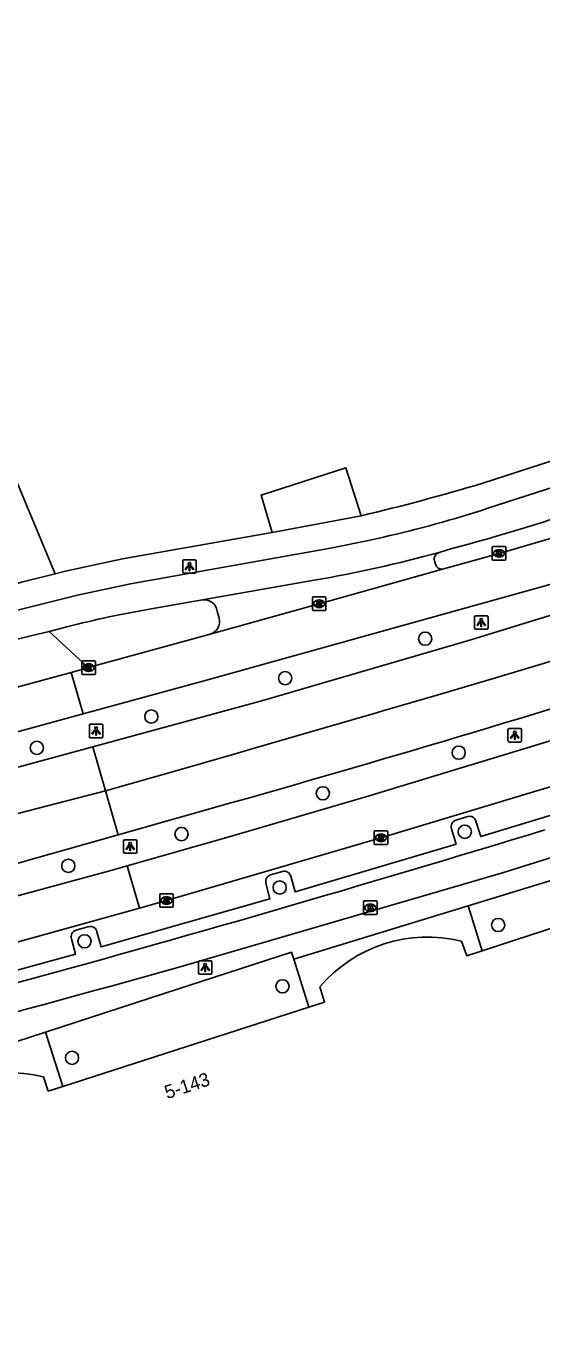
# Model space of a CAD drawing. Extents: x 159265 to 160143, y 383413 to 384319.
# Drawn here: x 159453.2 to 159491.4, y 383990 to 384086.5 of the extents above; entities that cross this region are included whole.
import ezdxf

# ---------------------------------------------------------------- set-up
doc = ezdxf.new("R2010")
doc.units = 0
for name, color, linetype in [('IMGEO_Boom', 7, 'Continuous'), ('IMGEO_Brandkraan', 7, 'Continuous'), ('IMGEO_Fietspad_gesloten', 7, 'Continuous'), ('IMGEO_Groenvoorziening', 7, 'Continuous'), ('IMGEO_Hek', 7, 'Continuous'), ('IMGEO_Kolk', 7, 'Continuous'), ('IMGEO_Lichtpunt', 7, 'Continuous'), ('IMGEO_OVBaan_gesloten', 7, 'Continuous'), ('IMGEO_Pand', 7, 'Continuous'), ('IMGEO_Pand_nummerreeks', 7, 'Continuous'), ('IMGEO_Parkeervlak_open', 7, 'Continuous'), ('IMGEO_Rijbaan_lokaal_gesloten', 7, 'Continuous'), ('IMGEO_Rijbaan_lokaal_open', 7, 'Continuous'), ('IMGEO_Voetpad_open', 7, 'Continuous')]:
    doc.layers.add(name, color=color, linetype=linetype)

msp = doc.modelspace()

# ---------------------------------------------------------------- linework, layer by layer
at = {"layer": 'IMGEO_Boom'}
for centre in [(159482.731, 384041.176), (159472.376, 384038.258), (159462.483, 384035.417), (159454.018, 384033.101), (159485.212, 384032.747), (159475.168, 384029.742), (159464.709, 384026.726), (159485.657, 384026.899), (159456.346, 384024.381), (159471.973, 384022.776), (159488.134, 384020.001), (159457.543, 384018.793), (159472.186, 384015.466), (159456.619, 384010.17)]:
    msp.add_circle(centre, 0.489, dxfattribs=at)
at = {"layer": 'IMGEO_Brandkraan'}
for p, q in [((159478.17, 384020.849), (159478.17, 384021.701)), ((159478.245, 384021.775), (159479.097, 384021.775)), ((159478.658, 384021.555), (159478.683, 384021.555)), ((159479.171, 384021.701), (159479.171, 384020.849)), ((159479.097, 384020.775), (159478.245, 384020.775)), ((159478.681, 384020.995), (159478.656, 384020.995))]:
    msp.add_line(p, q, dxfattribs=at)
for points in [[(159478.17, 384020.849), (159478.17, 384021.701)], [(159478.245, 384021.775), (159479.097, 384021.775)], [(159478.518, 384021.475), (159478.518, 384021.075), (159478.731, 384021.075)], [(159478.749, 384021.475), (159478.518, 384021.475)], [(159478.697, 384021.394), (159478.643, 384021.394), (159478.643, 384021.318)], [(159479.171, 384021.701), (159479.171, 384020.849)], [(159479.097, 384020.775), (159478.245, 384020.775)], [(159478.643, 384021.318), (159478.696, 384021.318)], [(159478.705, 384021.242), (159478.643, 384021.242), (159478.643, 384021.161)], [(159478.643, 384021.161), (159478.705, 384021.161)]]:
    msp.add_lwpolyline(points, dxfattribs=at)
for centre, radius, start, end in [((159478.247, 384021.699), 0.0765, 91.55205, 178.44795), ((159478.247, 384021.699), 0.0765, 91.55205, 178.44795), ((159478.698, 384021.356), 0.0379, 267.82845, 90.93552), ((159478.753, 384021.33), 0.145, 59.4692, 91.53667), ((159478.778, 384021.377), 0.0922, 285.51372, 58.15012), ((159479.095, 384021.699), 0.0765, 1.55205, 88.44795), ((159479.095, 384021.699), 0.0765, 1.55205, 88.44795), ((159478.247, 384020.851), 0.0765, 181.55205, 268.44795), ((159478.247, 384020.851), 0.0765, 181.55205, 268.44795), ((159478.706, 384021.201), 0.0404, 269.87594, 90.50774), ((159478.737, 384021.326), 0.251, 268.66757, 293.53466), ((159478.783, 384021.185), 0.105, 301.31148, 78.98903), ((159479.095, 384020.851), 0.0765, 271.55205, 358.44795), ((159479.095, 384020.851), 0.0765, 271.55205, 358.44795)]:
    msp.add_arc(centre, radius, start, end, dxfattribs=at)
for centre, major_axis, ratio, start_param, end_param in [((159478.657, 384021.275), (-0.387, 0.002), 0.722429, 4.712389, 7.853982), ((159478.682, 384021.275), (-0.39, 0.002), 0.717154, 1.570796, 4.712389)]:
    msp.add_ellipse(centre, major_axis=major_axis, ratio=ratio, start_param=start_param, end_param=end_param, dxfattribs=at)
at = {"layer": 'IMGEO_Fietspad_gesloten'}
for points in [[(159601.922, 384086.495), (159588.327, 384082.101), (159558.226, 384072.43), (159521.215, 384061.538), (159513.065, 384059.092), (159510.209, 384058.194), (159500, 384054.9), (159487.366, 384050.824)], [(159479.641, 384048.689), (159478.674, 384048.47), (159475.728, 384047.88), (159460.931, 384045.237), (159457.017, 384044.403), (159455.052, 384043.915), (159447.313, 384041.993), (159444.412, 384041.23), (159418.713, 384032.817)], [(159483.76, 384047.556), (159484.703, 384047.839)], [(159462.46, 384043.375), (159466.258, 384044.045)], [(159454.931, 384041.72), (159456.247, 384042.047)], [(159464.437, 384016.85), (159488.441, 384023.864), (159500.001, 384027.471), (159510.408, 384030.712), (159511.361, 384031.015)]]:
    msp.add_lwpolyline(points, dxfattribs=at)
for centre, radius, start, end in [((159461.446, 384129.565), 82.897, 282.6787, 288.22028), ((159446.013, 384193.507), 150.719, 284.87457, 289.05503), ((159473.295, 383977.486), 66.774, 99.33837, 104.79194), ((159100.262, 385302.997), 1334.613, 285.247753, 287.049896), ((158851.136, 386219.71), 2286.642, 284.531576, 285.557809)]:
    msp.add_arc(centre, radius, start, end, dxfattribs=at)
at = {"layer": 'IMGEO_Groenvoorziening'}
msp.add_lwpolyline([(159452.192, 384052.621), (159452.542, 384052.782), (159455.367, 384045.971)], dxfattribs=at)
at = {"layer": 'IMGEO_Hek'}
msp.add_lwpolyline([(159452.192, 384052.621), (159452.542, 384052.782), (159455.367, 384045.971)], dxfattribs=at)
at = {"layer": 'IMGEO_Kolk'}
for p, q in [((159487.695, 384047.067), (159487.695, 384047.919)), ((159487.77, 384047.993), (159488.622, 384047.993)), ((159488.183, 384047.773), (159488.208, 384047.773)), ((159488.696, 384047.919), (159488.696, 384047.067)), ((159488.622, 384046.993), (159487.77, 384046.993)), ((159488.206, 384047.213), (159488.181, 384047.213)), ((159474.394, 384043.34), (159474.394, 384044.192)), ((159474.469, 384044.266), (159475.321, 384044.266)), ((159474.882, 384044.046), (159474.907, 384044.046)), ((159475.395, 384044.192), (159475.395, 384043.34)), ((159475.321, 384043.266), (159474.469, 384043.266)), ((159474.905, 384043.486), (159474.88, 384043.486)), ((159457.348, 384038.611), (159457.348, 384039.463)), ((159457.423, 384039.537), (159458.275, 384039.537)), ((159457.859, 384038.757), (159457.834, 384038.757)), ((159457.836, 384039.317), (159457.861, 384039.317)), ((159458.349, 384039.463), (159458.349, 384038.611)), ((159458.275, 384038.537), (159457.423, 384038.537)), ((159478.959, 384026.029), (159478.959, 384026.881)), ((159479.034, 384026.955), (159479.886, 384026.955)), ((159479.47, 384026.175), (159479.445, 384026.175)), ((159479.447, 384026.735), (159479.472, 384026.735)), ((159479.96, 384026.881), (159479.96, 384026.029)), ((159479.886, 384025.955), (159479.034, 384025.955)), ((159463.175, 384022.31), (159464.027, 384022.31)), ((159463.1, 384021.384), (159463.1, 384022.236)), ((159463.611, 384021.53), (159463.586, 384021.53)), ((159463.588, 384022.09), (159463.613, 384022.09)), ((159464.101, 384022.236), (159464.101, 384021.384)), ((159464.027, 384021.31), (159463.175, 384021.31))]:
    msp.add_line(p, q, dxfattribs=at)
for points in [[(159487.695, 384047.067), (159487.695, 384047.919)], [(159487.77, 384047.993), (159488.622, 384047.993)], [(159488.016, 384047.693), (159488.139, 384047.693), (159488.139, 384047.542), (159488.269, 384047.693), (159488.433, 384047.693), (159488.287, 384047.542), (159488.44, 384047.293), (159488.288, 384047.293), (159488.203, 384047.457), (159488.139, 384047.39), (159488.139, 384047.293), (159488.016, 384047.293), (159488.016, 384047.693)], [(159488.696, 384047.919), (159488.696, 384047.067)], [(159488.622, 384046.993), (159487.77, 384046.993)], [(159474.394, 384043.34), (159474.394, 384044.192)], [(159474.469, 384044.266), (159475.321, 384044.266)], [(159474.715, 384043.966), (159474.838, 384043.966), (159474.838, 384043.815), (159474.968, 384043.966), (159475.132, 384043.966), (159474.986, 384043.815), (159475.139, 384043.566), (159474.987, 384043.566), (159474.902, 384043.73), (159474.838, 384043.663), (159474.838, 384043.566), (159474.715, 384043.566), (159474.715, 384043.966)], [(159475.395, 384044.192), (159475.395, 384043.34)], [(159475.321, 384043.266), (159474.469, 384043.266)], [(159457.348, 384038.611), (159457.348, 384039.463)], [(159457.423, 384039.537), (159458.275, 384039.537)], [(159457.669, 384039.237), (159457.792, 384039.237), (159457.792, 384039.086), (159457.922, 384039.237), (159458.086, 384039.237), (159457.94, 384039.086), (159458.093, 384038.837), (159457.941, 384038.837), (159457.856, 384039.001), (159457.792, 384038.934), (159457.792, 384038.837), (159457.669, 384038.837), (159457.669, 384039.237)], [(159458.349, 384039.463), (159458.349, 384038.611)], [(159458.275, 384038.537), (159457.423, 384038.537)], [(159478.959, 384026.029), (159478.959, 384026.881)], [(159479.034, 384026.955), (159479.886, 384026.955)], [(159479.28, 384026.655), (159479.403, 384026.655), (159479.403, 384026.504), (159479.533, 384026.655), (159479.697, 384026.655), (159479.551, 384026.504), (159479.704, 384026.255), (159479.552, 384026.255), (159479.467, 384026.419), (159479.403, 384026.352), (159479.403, 384026.255), (159479.28, 384026.255), (159479.28, 384026.655)], [(159479.96, 384026.881), (159479.96, 384026.029)], [(159479.886, 384025.955), (159479.034, 384025.955)], [(159463.175, 384022.31), (159464.027, 384022.31)], [(159463.1, 384021.384), (159463.1, 384022.236)], [(159463.421, 384022.01), (159463.544, 384022.01), (159463.544, 384021.859), (159463.674, 384022.01), (159463.838, 384022.01), (159463.692, 384021.859), (159463.845, 384021.61), (159463.693, 384021.61), (159463.608, 384021.774), (159463.544, 384021.707), (159463.544, 384021.61), (159463.421, 384021.61), (159463.421, 384022.01)], [(159464.101, 384022.236), (159464.101, 384021.384)], [(159464.027, 384021.31), (159463.175, 384021.31)]]:
    msp.add_lwpolyline(points, dxfattribs=at)
for centre, start, end in [((159487.772, 384047.917), 91.55205, 178.44795), ((159487.772, 384047.917), 91.55205, 178.44795), ((159488.62, 384047.917), 1.55205, 88.44795), ((159488.62, 384047.917), 1.55205, 88.44795), ((159487.772, 384047.069), 181.55205, 268.44795), ((159487.772, 384047.069), 181.55205, 268.44795), ((159488.62, 384047.069), 271.55205, 358.44795), ((159488.62, 384047.069), 271.55205, 358.44795), ((159474.471, 384044.19), 91.55205, 178.44795), ((159474.471, 384044.19), 91.55205, 178.44795), ((159475.319, 384044.19), 1.55205, 88.44795), ((159475.319, 384044.19), 1.55205, 88.44795), ((159474.471, 384043.342), 181.55205, 268.44795), ((159474.471, 384043.342), 181.55205, 268.44795), ((159475.319, 384043.342), 271.55205, 358.44795), ((159475.319, 384043.342), 271.55205, 358.44795), ((159457.425, 384039.461), 91.55205, 178.44795), ((159457.425, 384039.461), 91.55205, 178.44795), ((159458.273, 384039.461), 1.55205, 88.44795), ((159458.273, 384039.461), 1.55205, 88.44795), ((159457.425, 384038.613), 181.55205, 268.44795), ((159457.425, 384038.613), 181.55205, 268.44795), ((159458.273, 384038.613), 271.55205, 358.44795), ((159458.273, 384038.613), 271.55205, 358.44795), ((159479.036, 384026.879), 91.55205, 178.44795), ((159479.036, 384026.879), 91.55205, 178.44795), ((159479.884, 384026.879), 1.55205, 88.44795), ((159479.884, 384026.879), 1.55205, 88.44795), ((159479.036, 384026.031), 181.55205, 268.44795), ((159479.036, 384026.031), 181.55205, 268.44795), ((159479.884, 384026.031), 271.55205, 358.44795), ((159479.884, 384026.031), 271.55205, 358.44795), ((159463.177, 384022.234), 91.55205, 178.44795), ((159463.177, 384022.234), 91.55205, 178.44795), ((159464.025, 384022.234), 1.55205, 88.44795), ((159464.025, 384022.234), 1.55205, 88.44795), ((159463.177, 384021.386), 181.55205, 268.44795), ((159463.177, 384021.386), 181.55205, 268.44795), ((159464.025, 384021.386), 271.55205, 358.44795), ((159464.025, 384021.386), 271.55205, 358.44795)]:
    msp.add_arc(centre, 0.0765, start, end, dxfattribs=at)
for centre, major_axis, ratio, start_param, end_param in [((159488.182, 384047.493), (-0.387, 0.002), 0.722429, 4.712389, 7.853982), ((159488.207, 384047.493), (-0.39, 0.002), 0.717154, 1.570796, 4.712389), ((159474.881, 384043.766), (-0.387, 0.002), 0.722429, 4.712389, 7.853982), ((159474.906, 384043.766), (-0.39, 0.002), 0.717154, 1.570796, 4.712389), ((159457.835, 384039.037), (-0.387, 0.002), 0.722429, 4.712389, 7.853982), ((159457.86, 384039.037), (-0.39, 0.002), 0.717154, 1.570796, 4.712389), ((159479.446, 384026.455), (-0.387, 0.002), 0.722429, 4.712389, 7.853982), ((159479.471, 384026.455), (-0.39, 0.002), 0.717154, 1.570796, 4.712389), ((159463.587, 384021.81), (-0.387, 0.002), 0.722429, 4.712389, 7.853982), ((159463.612, 384021.81), (-0.39, 0.002), 0.717154, 1.570796, 4.712389)]:
    msp.add_ellipse(centre, major_axis=major_axis, ratio=ratio, start_param=start_param, end_param=end_param, dxfattribs=at)
at = {"layer": 'IMGEO_Lichtpunt'}
for p, q in [((159464.804, 384046.915), (159464.804, 384046.108)), ((159464.804, 384046.915), (159464.804, 384046.108)), ((159465.706, 384047.01), (159464.898, 384047.01)), ((159465.706, 384047.01), (159464.898, 384047.01)), ((159465.8, 384046.108), (159465.8, 384046.915)), ((159465.8, 384046.108), (159465.8, 384046.915)), ((159464.898, 384046.014), (159465.706, 384046.014)), ((159464.898, 384046.014), (159465.706, 384046.014)), ((159486.382, 384042.78), (159486.382, 384041.973)), ((159486.382, 384042.78), (159486.382, 384041.973)), ((159487.284, 384042.875), (159486.476, 384042.875)), ((159487.284, 384042.875), (159486.476, 384042.875)), ((159487.378, 384041.973), (159487.378, 384042.78)), ((159487.378, 384041.973), (159487.378, 384042.78)), ((159486.476, 384041.879), (159487.284, 384041.879)), ((159486.476, 384041.879), (159487.284, 384041.879)), ((159458.801, 384034.849), (159457.993, 384034.849)), ((159458.801, 384034.849), (159457.993, 384034.849)), ((159457.899, 384034.754), (159457.899, 384033.947)), ((159457.899, 384034.754), (159457.899, 384033.947)), ((159458.895, 384033.947), (159458.895, 384034.754)), ((159458.895, 384033.947), (159458.895, 384034.754)), ((159488.856, 384034.437), (159488.856, 384033.63)), ((159488.856, 384034.437), (159488.856, 384033.63)), ((159489.758, 384034.532), (159488.95, 384034.532)), ((159489.758, 384034.532), (159488.95, 384034.532)), ((159489.852, 384033.63), (159489.852, 384034.437)), ((159489.852, 384033.63), (159489.852, 384034.437)), ((159457.993, 384033.853), (159458.801, 384033.853)), ((159457.993, 384033.853), (159458.801, 384033.853)), ((159488.95, 384033.536), (159489.758, 384033.536)), ((159488.95, 384033.536), (159489.758, 384033.536)), ((159460.427, 384026.211), (159460.427, 384025.404)), ((159460.427, 384026.211), (159460.427, 384025.404)), ((159461.329, 384026.306), (159460.521, 384026.306)), ((159461.329, 384026.306), (159460.521, 384026.306)), ((159461.423, 384025.404), (159461.423, 384026.211)), ((159461.423, 384025.404), (159461.423, 384026.211)), ((159460.521, 384025.31), (159461.329, 384025.31)), ((159460.521, 384025.31), (159461.329, 384025.31)), ((159465.97, 384017.261), (159465.97, 384016.454)), ((159465.97, 384017.261), (159465.97, 384016.454)), ((159466.872, 384017.356), (159466.064, 384017.356)), ((159466.872, 384017.356), (159466.064, 384017.356)), ((159466.966, 384016.454), (159466.966, 384017.261)), ((159466.966, 384016.454), (159466.966, 384017.261)), ((159466.064, 384016.36), (159466.872, 384016.36)), ((159466.064, 384016.36), (159466.872, 384016.36))]:
    msp.add_line(p, q, dxfattribs=at)
for points in [[(159465.178, 384046.579), (159465.217, 384046.551), (159465.029, 384046.289), (159464.991, 384046.316), (159465.178, 384046.579)], [(159465.28, 384046.531), (159465.327, 384046.531), (159465.327, 384046.209), (159465.28, 384046.209), (159465.28, 384046.531)], [(159465.39, 384046.551), (159465.428, 384046.578), (159465.615, 384046.316), (159465.576, 384046.288), (159465.39, 384046.551)], [(159486.756, 384042.444), (159486.795, 384042.416), (159486.607, 384042.154), (159486.569, 384042.181), (159486.756, 384042.444)], [(159486.858, 384042.396), (159486.905, 384042.396), (159486.905, 384042.074), (159486.858, 384042.074), (159486.858, 384042.396)], [(159486.968, 384042.416), (159487.006, 384042.443), (159487.193, 384042.181), (159487.154, 384042.153), (159486.968, 384042.416)], [(159458.273, 384034.418), (159458.312, 384034.39), (159458.124, 384034.128), (159458.086, 384034.155), (159458.273, 384034.418)], [(159458.375, 384034.37), (159458.422, 384034.37), (159458.422, 384034.048), (159458.375, 384034.048), (159458.375, 384034.37)], [(159458.485, 384034.39), (159458.523, 384034.417), (159458.71, 384034.155), (159458.671, 384034.127), (159458.485, 384034.39)], [(159489.23, 384034.101), (159489.269, 384034.073), (159489.081, 384033.811), (159489.043, 384033.838), (159489.23, 384034.101)], [(159489.332, 384034.053), (159489.379, 384034.053), (159489.379, 384033.731), (159489.332, 384033.731), (159489.332, 384034.053)], [(159489.442, 384034.073), (159489.48, 384034.1), (159489.667, 384033.838), (159489.628, 384033.81), (159489.442, 384034.073)], [(159460.801, 384025.875), (159460.84, 384025.847), (159460.652, 384025.585), (159460.614, 384025.612), (159460.801, 384025.875)], [(159460.903, 384025.827), (159460.95, 384025.827), (159460.95, 384025.505), (159460.903, 384025.505), (159460.903, 384025.827)], [(159461.013, 384025.847), (159461.051, 384025.874), (159461.238, 384025.612), (159461.199, 384025.584), (159461.013, 384025.847)], [(159466.344, 384016.925), (159466.383, 384016.897), (159466.195, 384016.635), (159466.157, 384016.662), (159466.344, 384016.925)], [(159466.446, 384016.877), (159466.493, 384016.877), (159466.493, 384016.555), (159466.446, 384016.555), (159466.446, 384016.877)], [(159466.556, 384016.897), (159466.594, 384016.924), (159466.781, 384016.662), (159466.742, 384016.634), (159466.556, 384016.897)]]:
    msp.add_lwpolyline(points, dxfattribs=at)
for centre in [(159465.303, 384046.713), (159486.881, 384042.578), (159458.398, 384034.552), (159489.355, 384034.235), (159460.926, 384026.009), (159466.469, 384017.059)]:
    msp.add_circle(centre, 0.0994, dxfattribs=at)
for centre, start, end in [((159464.898, 384046.915), 90, 180), ((159464.898, 384046.915), 90, 180), ((159465.706, 384046.915), 0, 90), ((159465.706, 384046.915), 0, 90), ((159464.898, 384046.108), 180, 270), ((159464.898, 384046.108), 180, 270), ((159465.706, 384046.108), 270, 0), ((159465.706, 384046.108), 270, 360), ((159486.476, 384042.78), 90, 180), ((159486.476, 384042.78), 90, 180), ((159487.284, 384042.78), 0, 90), ((159487.284, 384042.78), 0, 90), ((159486.476, 384041.973), 180, 270), ((159486.476, 384041.973), 180, 270), ((159487.284, 384041.973), 270, 0), ((159487.284, 384041.973), 270, 360), ((159457.993, 384034.754), 90, 180), ((159457.993, 384034.754), 90, 180), ((159458.801, 384034.754), 0, 90), ((159458.801, 384034.754), 0, 90), ((159457.993, 384033.947), 180, 270), ((159457.993, 384033.947), 180, 270), ((159458.801, 384033.947), 270, 0), ((159458.801, 384033.947), 270, 360), ((159488.95, 384034.437), 90, 180), ((159488.95, 384034.437), 90, 180), ((159489.758, 384034.437), 0, 90), ((159489.758, 384034.437), 0, 90), ((159488.95, 384033.63), 180, 270), ((159488.95, 384033.63), 180, 270), ((159489.758, 384033.63), 270, 0), ((159489.758, 384033.63), 270, 360), ((159460.521, 384026.211), 90, 180), ((159460.521, 384026.211), 90, 180), ((159461.329, 384026.211), 0, 90), ((159461.329, 384026.211), 0, 90), ((159460.521, 384025.404), 180, 270), ((159460.521, 384025.404), 180, 270), ((159461.329, 384025.404), 270, 0), ((159461.329, 384025.404), 270, 360), ((159466.064, 384017.261), 90, 180), ((159466.064, 384017.261), 90, 180), ((159466.872, 384017.261), 0, 90), ((159466.872, 384017.261), 0, 90), ((159466.064, 384016.454), 180, 270), ((159466.064, 384016.454), 180, 270), ((159466.872, 384016.454), 270, 0), ((159466.872, 384016.454), 270, 360)]:
    msp.add_arc(centre, 0.0946, start, end, dxfattribs=at)
at = {"layer": 'IMGEO_OVBaan_gesloten'}
for points in [[(159512.459, 384049.591), (159509.372, 384048.571), (159505.045, 384047.187), (159500, 384045.601), (159497.73, 384044.887), (159497.798, 384044.69), (159486.108, 384041.085), (159470.738, 384036.595), (159458.156, 384033.181)], [(159513.523, 384046.314), (159498.741, 384041.516), (159497.418, 384041.118), (159493.036, 384039.81), (159488.599, 384038.486), (159487.855, 384038.264), (159483.684, 384037.037), (159479.605, 384035.835), (159478.89, 384035.627), (159478.28, 384035.448), (159474.351, 384034.31), (159470.02, 384033.052), (159469.354, 384032.862), (159468.693, 384032.67), (159464.384, 384031.44), (159459.096, 384029.931)], [(159458.156, 384033.181), (159443.352, 384029.163)], [(159459.096, 384029.931), (159458.156, 384033.181)], [(159296.996, 383990.046), (159393.277, 384012.905), (159459.096, 384029.931)], [(159459.096, 384029.931), (159460.036, 384026.681)], [(159460.036, 384026.681), (159463.863, 384027.763)], [(159445.184, 384022.484), (159460.036, 384026.681)]]:
    msp.add_lwpolyline(points, dxfattribs=at)
msp.add_arc((159133.691, 385211.565), 1228.984, 285.584211, 287.325588, dxfattribs=at)
at = {"layer": 'IMGEO_Pand'}
for points in [[(159505.079, 384024.007), (159500, 384022.352), (159486.942, 384018.097)], [(159485.415, 384018.803), (159485.804, 384017.726), (159486.942, 384018.097)], [(159474.14, 384013.927), (159475.292, 384014.298), (159474.943, 384015.424)], [(159474.14, 384013.927), (159455.939, 384008.057)], [(159454.511, 384008.76), (159454.865, 384007.711), (159455.939, 384008.057)]]:
    msp.add_lwpolyline(points, dxfattribs=at)
for centre, radius, start, end in [((159482.908, 384008.656), 10.452, 76.12184, 139.64483), ((159451.976, 383998.632), 10.44, 75.94599, 139.678)]:
    msp.add_arc(centre, radius, start, end, dxfattribs=at)
at = {"layer": 'IMGEO_Parkeervlak_open'}
for points in [[(159498.622, 384030.114), (159486.843, 384026.535), (159486.478, 384027.673)], [(159485.894, 384028.023), (159485.007, 384027.753)], [(159484.67, 384027.114), (159485.018, 384025.98), (159473.116, 384022.453), (159472.787, 384023.6)], [(159472.174, 384023.969), (159471.286, 384023.708)], [(159470.956, 384023.083), (159471.255, 384021.926), (159462.156, 384019.353), (159458.766, 384018.394), (159458.461, 384019.498)], [(159457.851, 384019.876), (159456.914, 384019.611)], [(159456.573, 384018.975), (159456.888, 384017.846), (159451.016, 384016.243), (159444.409, 384014.439), (159444.106, 384015.569)]]:
    msp.add_lwpolyline(points, dxfattribs=at)
for centre, radius, start, end in [((159485.161, 384027.264), 0.513, 107.43239, 196.95449), ((159486.021, 384027.573), 0.467, 12.31308, 105.81714), ((159471.448, 384023.223), 0.512, 108.49783, 195.83406), ((159472.309, 384023.5), 0.488, 11.86229, 106.0454), ((159457.055, 384019.126), 0.505, 106.20109, 197.40173), ((159457.982, 384019.407), 0.487, 10.78372, 105.64559)]:
    msp.add_arc(centre, radius, start, end, dxfattribs=at)
at = {"layer": 'IMGEO_Rijbaan_lokaal_gesloten'}
for points in [[(159510.834, 384054.508), (159505.885, 384052.912), (159500, 384051.006), (159498.039, 384050.371), (159488.196, 384047.492), (159484.02, 384046.333)], [(159457.449, 384035.626), (159466.568, 384038.12), (159491.771, 384045.13), (159495.609, 384046.257), (159499.447, 384047.435), (159500, 384047.613), (159511.853, 384051.439)], [(159484.02, 384046.333), (159474.895, 384043.765), (159466.828, 384041.507)], [(159466.828, 384041.507), (159457.849, 384039.037), (159457.608, 384038.971)], [(159515.176, 384040.921), (159500, 384036.064), (159478.341, 384029.48), (159468.247, 384026.53), (159460.703, 384024.378)], [(159457.608, 384038.971), (159456.564, 384038.686)], [(159456.564, 384038.686), (159454.456, 384038.11), (159446.577, 384035.956), (159445.699, 384035.714), (159445.098, 384035.548), (159439.129, 384033.948)], [(159456.564, 384038.686), (159457.449, 384035.626)], [(159442.646, 384031.576), (159457.449, 384035.626)], [(159461.606, 384021.256), (159463.601, 384021.812), (159479.46, 384026.454), (159493.27, 384030.606), (159500, 384032.668), (159501.087, 384033.001)], [(159460.703, 384024.378), (159459.582, 384024.058), (159445.759, 384020.312)], [(159460.703, 384024.378), (159461.606, 384021.256)], [(159408.465, 384007.147), (159419.249, 384009.943), (159435.196, 384014.035), (159450.04, 384018.032), (159461.606, 384021.256)]]:
    msp.add_lwpolyline(points, dxfattribs=at)
at = {"layer": 'IMGEO_Rijbaan_lokaal_open'}
for points in [[(159471.409, 384049.042), (159470.598, 384051.803), (159476.862, 384053.819), (159478.005, 384050.268)], [(159471.409, 384049.042), (159478.005, 384050.268)], [(159483.414, 384046.926), (159483.494, 384046.679)], [(159466.258, 384044.045), (159474.533, 384045.509)], [(159467.504, 384042.693), (159467.356, 384043.222)], [(159439.475, 384037.267), (159444.707, 384038.927), (159447.905, 384039.941), (159451.516, 384040.86), (159453.578, 384041.384), (159454.931, 384041.72)], [(159454.931, 384041.72), (159457.469, 384039.361), (159457.608, 384038.971)]]:
    msp.add_lwpolyline(points, dxfattribs=at)
for centre, radius, start, end in [((159458.155, 384141.155), 97.038, 279.71707, 285.29978), ((159483.925, 384047.055), 0.527, 108.26339, 194.18487), ((159483.942, 384046.787), 0.461, 193.58293, 279.74365), ((159466.401, 384043.092), 0.964, 7.7755, 98.51811), ((159466.516, 384042.47), 1.012, 287.92614, 12.70904)]:
    msp.add_arc(centre, radius, start, end, dxfattribs=at)
at = {"layer": 'IMGEO_Voetpad_open'}
for points in [[(159487.001, 384052.689), (159500, 384056.891), (159511.609, 384060.643), (159543.362, 384070.117), (159558.885, 384074.794), (159579.768, 384081.482)], [(159455.367, 384045.971), (159456.144, 384046.166), (159460.351, 384047.095), (159471.265, 384049.015), (159471.409, 384049.042)], [(159452.061, 384045.137), (159452.628, 384045.293), (159452.895, 384045.35), (159455.367, 384045.971)], [(159485.905, 384021.419), (159500, 384025.736), (159504.195, 384027.021), (159505.079, 384024.007)], [(159473.008, 384017.469), (159485.905, 384021.419)], [(159486.942, 384018.097), (159485.905, 384021.419)], [(159454.659, 384012.066), (159463.437, 384014.923), (159472.843, 384017.985), (159473.008, 384017.469)], [(159473.008, 384017.469), (159474.14, 384013.927)], [(159441.915, 384007.926), (159454.659, 384012.066)], [(159455.939, 384008.057), (159454.659, 384012.066)]]:
    msp.add_lwpolyline(points, dxfattribs=at)
msp.add_arc((159441.589, 384203.506), 157.506, 283.36785, 286.75725, dxfattribs=at)

# ---------------------------------------------------------------- texts
at = {"layer": 'IMGEO_Pand_nummerreeks'}
msp.add_text('5-143', height=1, rotation=18.00533, dxfattribs=at).set_placement((159463.651, 384007.113))

doc.saveas('drawing.dxf')
